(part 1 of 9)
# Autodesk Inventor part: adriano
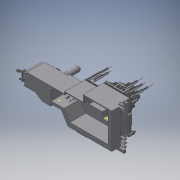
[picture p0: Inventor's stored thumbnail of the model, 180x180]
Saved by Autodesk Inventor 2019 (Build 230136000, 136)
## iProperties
Created: 2014-11
Part Number: adriano
Material: 一般
Document SubType Name: Modeling
Designer: Kikut
Density: 1 g/cm^3
Appearance: 既定
Author: Kikut
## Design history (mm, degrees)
sketch "スケッチ1"
  geometry: 1 further point
sketch "スケッチ2"
  geometry: L1 (-119.588, 39.314)-(-119.588, -40.686); L2 (-119.588, -40.686)-(-19.588, -40.686); L3 (-19.588, -40.686)-(-4.588, -15.686); L4 (-4.588, -15.686)-(20.412, -15.686); L5 (20.412, -15.686)-(20.412, 19.314); L6 (20.412, 19.314)-(-11.588, 19.314); L7 (-11.588, 19.314)-(-11.588, 24.314); L8 (-11.588, 24.314)-(-54.588, 24.314); L9 (-54.588, 24.314)-(-54.588, 39.314); L10 (-54.588, 39.314)-(-119.588, 39.314); 1 further point
  constraints: 20 end point, 7 parallel, 1 perpendicular, 1 vertical
  dimensions: "d0" = 80 distance of L1.start L1.end; "d2" = 100 distance of L1.end L2.end; "d3" = 25 distance of L3.end L4.end; "d4" = 35 distance of L4.end L5.end; "d5" = 65 distance of L9.end L1.start; "d6" = 15 distance of L8.end L9.end; "d7" = 43 distance of L7.end L8.end; "d8" = 32 distance of L5.end L6.end; "d9" = 5 distance of L6.end L7.end
extrude "押し出し1" new body sketch "スケッチ2" distance "d10" = 20; taper "d11" = 0 deg
sketch "スケッチ3"
  geometry: L1 (119.588, -39.314)-(119.588, 40.686) reference; L2 (119.588, 40.686)-(19.588, 40.686) reference; L3 (19.588, 40.686)-(4.588, 15.686) reference; L4 (-20.412, 15.686)-(-20.412, -19.314) reference; L5 (-20.412, -19.314)-(11.588, -19.314) reference; L6 (11.588, -19.314)-(11.588, -24.314) reference; L7 (11.588, -24.314)-(54.588, -24.314) reference; L8 (54.588, -24.314)-(54.588, -39.314) reference; L9 (54.588, -39.314)-(119.588, -39.314) reference; L10 (-20.412, -19.314)-(11.588, -19.314); L11 (11.588, -19.314)-(11.588, -24.314); L12 (11.588, -24.314)-(54.588, -24.314); L13 (54.588, -24.314)-(54.588, -39.314); L14 (54.588, -39.314)-(114.588, -39.314); L15 (114.588, -39.314)-(114.588, 32.686); L16 (114.588, 32.686)-(24.588, 32.686); L17 (24.588, 32.686)-(11.388, 10.686); L18 (11.388, 10.686)-(-20.412, 10.686); L19 (-20.412, 10.686)-(-20.412, -19.314); 1 further point
  constraints: 20 end point, 4 parallel, 4 perpendicular, 2 collinear
  dimensions: "d12" = 30 distance of L18.end L10.start; "d14" = 0 distance between parallel lines of L5 L10; "d15" = 0 distance between parallel lines of L11 L6; "d16" = 0 distance between parallel lines of L12 L7; "d17" = 0 distance between parallel lines of L13 L8; "d18" = 0 distance between parallel lines of L14 L9; "d19" = 5 distance between parallel lines of L1 L15; "d20" = 8 distance between parallel lines of L16 L2; "d21" = 0 distance between parallel lines of L4 L19; "d22" = 90 distance of L15.end L16.end; "d98" = 31.8 distance of L17.end L18.end (derived)
extrude "押し出し2" join sketch "スケッチ3" distance "d23" = 30; taper "d24" = 0 deg
sketch "スケッチ4"
  geometry: L1 (119.588, -39.314)-(119.588, 40.686) reference; L2 (119.588, 40.686)-(19.588, 40.686) reference; L3 (24.588, 32.686)-(114.588, 32.686) reference; L4 (38.588, 40.686)-(103.588, 40.686); L5 (103.588, 40.686)-(103.588, 32.686); L6 (103.588, 32.686)-(38.588, 32.686); L7 (38.588, 32.686)-(38.588, 40.686); 1 further point
  constraints: 8 end point, 2 parallel, 1 horizontal, 1 perpendicular, 1 point on line
  dimensions: "d25" = 0 distance between parallel lines of L3 L6; "d26" = 16 distance between parallel lines of L1 L5; "d27" = 65 distance between parallel lines of L5 L7
extrude "step00" join sketch "スケッチ4" distance "d28" = 1; taper "d29" = 0 deg
sketch "スケッチ5"
  geometry: L1 (38.588, 40.686)-(38.588, 32.686) reference; L2 (103.588, 32.686)-(38.588, 32.686) reference; L3 (103.588, 32.686)-(103.588, 40.686) reference; L4 (103.588, 40.686)-(38.588, 40.686) reference; L5 (39.588, 40.686)-(102.588, 40.686); L6 (102.588, 40.686)-(102.588, 32.686); L7 (102.588, 32.686)-(39.588, 32.686); L8 (39.588, 32.686)-(39.588, 40.686); 1 further point
  constraints: 8 end point, 2 parallel, 2 point on line, 1 horizontal, 1 perpendicular
  dimensions: "d30" = 1 distance between parallel lines of L3 L6; "d31" = 1 distance between parallel lines of L8 L1
extrude "押し出し4" join sketch "スケッチ5" distance "d32" = 1; taper "d33" = 0 deg
sketch "スケッチ6"
  geometry: L1 (102.588, 32.686)-(102.588, 40.686) reference; L2 (102.588, 40.686)-(39.588, 40.686) reference; L3 (39.588, 40.686)-(39.588, 32.686) reference; L4 (102.588, 32.686)-(39.588, 32.686) reference; L5 (40.588, 40.686)-(101.588, 40.686); L6 (101.588, 40.686)-(101.588, 32.686); L7 (101.588, 32.686)-(40.588, 32.686); L8 (40.588, 32.686)-(40.588, 40.686); 1 further point
  constraints: 8 end point, 2 parallel, 2 point on line, 1 horizontal, 1 perpendicular
  dimensions: "d34" = 1 distance between parallel lines of L8 L3; "d35" = 1 distance between parallel lines of L1 L6
extrude "押し出し5" join sketch "スケッチ6" distance "d36" = 1; taper "d37" = 0 deg
sketch "スケッチ7"
  geometry: L1 (40.588, 40.686)-(40.588, 32.686) reference; L2 (101.588, 32.686)-(40.588, 32.686) reference; L3 (101.588, 32.686)-(101.588, 40.686) reference; L4 (101.588, 40.686)-(40.588, 40.686) reference; L5 (41.588, 40.686)-(100.588, 40.686); L6 (100.588, 40.686)-(100.588, 32.686); L7 (100.588, 32.686)-(41.588, 32.686); L8 (41.588, 32.686)-(41.588, 40.686); 1 further point
  constraints: 8 end point, 2 parallel, 2 point on line, 1 horizontal, 1 perpendicular
  dimensions: "d38" = 1 distance between parallel lines of L8 L1; "d39" = 1 distance between parallel lines of L3 L6
extrude "押し出し6" join sketch "スケッチ7" distance "d40" = 1; taper "d41" = 0 deg
sketch "スケッチ8"
  geometry: L1 (100.588, 32.686)-(100.588, 40.686) reference; L2 (100.588, 40.686)-(41.588, 40.686) reference; L3 (41.588, 40.686)-(41.588, 32.686) reference; L4 (100.588, 32.686)-(41.588, 32.686) reference; L5 (42.588, 40.686)-(99.588, 40.686); L6 (99.588, 40.686)-(99.588, 32.686); L7 (99.588, 32.686)-(42.588, 32.686); L8 (42.588, 32.686)-(42.588, 40.686); 1 further point
  constraints: 8 end point, 2 parallel, 2 point on line, 1 horizontal, 1 perpendicular
  dimensions: "d42" = 1 distance between parallel lines of L8 L3; "d43" = 1 distance between parallel lines of L1 L6
extrude "押し出し7" join sketch "スケッチ8" distance "d44" = 1; taper "d45" = 0 deg
sketch "スケッチ9"
  geometry: L1 (42.588, 40.686)-(42.588, 32.686) reference; L2 (99.588, 32.686)-(42.588, 32.686) reference; L3 (99.588, 32.686)-(99.588, 40.686) reference; L4 (99.588, 40.686)-(42.588, 40.686) reference; L5 (43.588, 40.686)-(98.588, 40.686); L6 (98.588, 40.686)-(98.588, 32.686); L7 (98.588, 32.686)-(43.588, 32.686); L8 (43.588, 32.686)-(43.588, 40.686); 1 further point
  constraints: 8 end point, 2 parallel, 2 point on line, 1 horizontal, 1 perpendicular
  dimensions: "d46" = 1 distance between parallel lines of L8 L1; "d47" = 1 distance between parallel lines of L3 L6
extrude "押し出し8" join sketch "スケッチ9" distance "d48" = 1; taper "d49" = 0 deg
sketch "スケッチ10"
  geometry: L1 (98.588, 32.686)-(98.588, 40.686) reference; L2 (98.588, 40.686)-(43.588, 40.686) reference; L3 (43.588, 40.686)-(43.588, 32.686) reference; L4 (98.588, 32.686)-(43.588, 32.686) reference; L5 (44.588, 40.686)-(97.588, 40.686); L6 (97.588, 40.686)-(97.588, 32.686); L7 (97.588, 32.686)-(44.588, 32.686); L8 (44.588, 32.686)-(44.588, 40.686); 1 further point
  constraints: 8 end point, 2 parallel, 2 point on line, 1 horizontal, 1 perpendicular
  dimensions: "d50" = 1 distance between parallel lines of L3 L8; "d51" = 1 distance between parallel lines of L1 L6
extrude "押し出し9" join sketch "スケッチ10" distance "d52" = 1; taper "d53" = 0 deg
sketch "スケッチ11"
  geometry: L1 (44.588, 40.686)-(44.588, 32.686) reference; L2 (97.588, 32.686)-(44.588, 32.686) reference; L3 (97.588, 32.686)-(97.588, 40.686) reference; L4 (97.588, 40.686)-(44.588, 40.686) reference; L5 (45.588, 40.686)-(96.588, 40.686); L6 (96.588, 40.686)-(96.588, 32.686); L7 (96.588, 32.686)-(45.588, 32.686); L8 (45.588, 32.686)-(45.588, 40.686); 1 further point
  constraints: 8 end point, 2 parallel, 2 point on line, 1 horizontal, 1 perpendicular
  dimensions: "d54" = 1 distance between parallel lines of L1 L8; "d55" = 1 distance between parallel lines of L3 L6
extrude "押し出し10" join sketch "スケッチ11" distance "d56" = 1; taper "d57" = 0 deg
sketch "スケッチ12"
  geometry: L1 (96.588, 32.686)-(96.588, 40.686) reference; L2 (96.588, 40.686)-(45.588, 40.686) reference; L3 (45.588, 40.686)-(45.588, 32.686) reference; L4 (96.588, 32.686)-(45.588, 32.686) reference; L5 (46.588, 40.686)-(95.588, 40.686); L6 (95.588, 40.686)-(95.588, 32.686); L7 (95.588, 32.686)-(46.588, 32.686); L8 (46.588, 32.686)-(46.588, 40.686); 1 further point
  constraints: 8 end point, 2 parallel, 2 point on line, 1 horizontal, 1 perpendicular
  dimensions: "d58" = 1 distance between parallel lines of L8 L3; "d59" = 1 distance between parallel lines of L1 L6
extrude "押し出し11" join sketch "スケッチ12" distance "d60" = 1; taper "d61" = 0 deg
sketch "スケッチ13"
  geometry: L1 (46.588, 40.686)-(46.588, 32.686) reference; L2 (95.588, 32.686)-(46.588, 32.686) reference; L3 (95.588, 32.686)-(95.588, 40.686) reference; L4 (95.588, 40.686)-(46.588, 40.686) reference; L5 (47.588, 40.686)-(94.588, 40.686); L6 (94.588, 40.686)-(94.588, 32.686); L7 (94.588, 32.686)-(47.588, 32.686); L8 (47.588, 32.686)-(47.588, 40.686); 1 further point
  constraints: 8 end point, 2 parallel, 2 point on line, 1 horizontal, 1 perpendicular
  dimensions: "d62" = 1 distance between parallel lines of L8 L1; "d63" = 1 distance between parallel lines of L3 L6
extrude "押し出し12" join sketch "スケッチ13" distance "d64" = 1; taper "d65" = 0 deg
sketch "スケッチ14"
  geometry: L1 (94.588, 32.686)-(94.588, 40.686) reference; L2 (94.588, 40.686)-(47.588, 40.686) reference; L3 (47.588, 40.686)-(47.588, 32.686) reference; L4 (94.588, 32.686)-(47.588, 32.686) reference; L5 (48.588, 40.686)-(93.588, 40.686); L6 (93.588, 40.686)-(93.588, 32.686); L7 (93.588, 32.686)-(48.588, 32.686); L8 (48.588, 32.686)-(48.588, 40.686); 1 further point
  constraints: 8 end point, 2 parallel, 2 point on line, 1 horizontal, 1 perpendicular
  dimensions: "d66" = 1 distance between parallel lines of L8 L3; "d67" = 1 distance between parallel lines of L1 L6
extrude "押し出し13" join sketch "スケッチ14" distance "d68" = 1; taper "d69" = 0 deg
sketch "スケッチ15"
  geometry: L1 (48.588, 40.686)-(48.588, 32.686) reference; L2 (93.588, 32.686)-(48.588, 32.686) reference; L3 (93.588, 32.686)-(93.588, 40.686) reference; L4 (93.588, 40.686)-(48.588, 40.686) reference; L5 (49.588, 40.686)-(92.588, 40.686); L6 (92.588, 40.686)-(92.588, 32.686); L7 (92.588, 32.686)-(49.588, 32.686); L8 (49.588, 32.686)-(49.588, 40.686); 1 further point
  constraints: 8 end point, 2 parallel, 2 point on line, 1 horizontal, 1 perpendicular
  dimensions: "d70" = 1 distance between parallel lines of L8 L1; "d71" = 1 distance between parallel lines of L6 L3
extrude "押し出し14" join sketch "スケッチ15" distance "d72" = 1; taper "d73" = 0 deg
sketch "スケッチ16"
  geometry: L1 (92.588, 32.686)-(92.588, 40.686) reference; L2 (92.588, 40.686)-(49.588, 40.686) reference; L3 (49.588, 40.686)-(49.588, 32.686) reference; L4 (92.588, 32.686)-(49.588, 32.686) reference; L5 (50.588, 40.686)-(91.588, 40.686); L6 (91.588, 40.686)-(91.588, 32.686); L7 (91.588, 32.686)-(50.588, 32.686); L8 (50.588, 32.686)-(50.588, 40.686); 1 further point
  constraints: 8 end point, 2 parallel, 2 point on line, 1 horizontal, 1 perpendicular
  dimensions: "d74" = 1 distance between parallel lines of L8 L3; "d75" = 1 distance between parallel lines of L1 L6
extrude "押し出し15" join sketch "スケッチ16" distance "d76" = 1; taper "d77" = 0 deg
sketch "スケッチ17"
  geometry: L1 (50.588, 40.686)-(50.588, 32.686) reference; L2 (91.588, 32.686)-(50.588, 32.686) reference; L3 (91.588, 32.686)-(91.588, 40.686) reference; L4 (91.588, 40.686)-(50.588, 40.686) reference; L5 (51.588, 40.686)-(90.588, 40.686); L6 (90.588, 40.686)-(90.588, 32.686); L7 (90.588, 32.686)-(51.588, 32.686); L8 (51.588, 32.686)-(51.588, 40.686); 1 further point
  constraints: 8 end point, 2 parallel, 2 point on line, 1 horizontal, 1 perpendicular
  dimensions: "d78" = 1 distance between parallel lines of L8 L1; "d79" = 1 distance between parallel lines of L3 L6
extrude "押し出し16" join sketch "スケッチ17" distance "d80" = 1; taper "d81" = 0 deg
sketch "スケッチ18"
  geometry: L1 (90.588, 32.686)-(90.588, 40.686) reference; L2 (90.588, 40.686)-(51.588, 40.686) reference; L3 (51.588, 40.686)-(51.588, 32.686) reference; L4 (90.588, 32.686)-(51.588, 32.686) reference; L5 (52.588, 40.686)-(89.588, 40.686); L6 (89.588, 40.686)-(89.588, 32.686); L7 (89.588, 32.686)-(52.588, 32.686); L8 (52.588, 32.686)-(52.588, 40.686); 1 further point
  constraints: 8 end point, 2 parallel, 2 point on line, 1 horizontal, 1 perpendicular
  dimensions: "d82" = 1 distance between parallel lines of L8 L3; "d83" = 1 distance between parallel lines of L1 L6
extrude "押し出し17" join sketch "スケッチ18" distance "d84" = 1; taper "d85" = 0 deg
sketch "スケッチ19"
  geometry: L1 (52.588, 40.686)-(52.588, 32.686) reference; L2 (89.588, 32.686)-(52.588, 32.686) reference; L3 (89.588, 32.686)-(89.588, 40.686) reference; L4 (89.588, 40.686)-(52.588, 40.686) reference; L5 (53.588, 40.686)-(88.588, 40.686); L6 (88.588, 40.686)-(88.588, 32.686); L7 (88.588, 32.686)-(53.588, 32.686); L8 (53.588, 32.686)-(53.588, 40.686); 1 further point
  constraints: 8 end point, 2 parallel, 2 point on line, 1 horizontal, 1 perpendicular
  dimensions: "d86" = 1 distance between parallel lines of L8 L1; "d87" = 1 distance between parallel lines of L3 L6
extrude "押し出し18" join sketch "スケッチ19" distance "d88" = 1; taper "d89" = 0 deg
sketch "スケッチ20"
  geometry: L1 (88.588, 32.686)-(88.588, 40.686) reference; L2 (88.588, 40.686)-(53.588, 40.686) reference; L3 (53.588, 40.686)-(53.588, 32.686) reference; L4 (88.588, 32.686)-(53.588, 32.686) reference; L5 (54.588, 40.686)-(87.588, 40.686); L6 (87.588, 40.686)-(87.588, 32.686); L7 (87.588, 32.686)-(54.588, 32.686); L8 (54.588, 32.686)-(54.588, 40.686); 1 further point
  constraints: 8 end point, 2 parallel, 2 point on line, 1 horizontal, 1 perpendicular
  dimensions: "d90" = 1 distance between parallel lines of L3 L8; "d91" = 1 distance between parallel lines of L1 L6
extrude "step" join sketch "スケッチ20" distance "d92" = 1; taper "d93" = 0 deg
sketch "スケッチ21"
  geometry: L1 (72, 0)-(0, 0) reference; L2 (72, 0)-(72, 30) reference; L3 (0, 30)-(72, 30) reference; L4 (0, 0)-(0, 30) reference; L5 (22, 30)-(50, 30); L6 (50, 30)-(50, 0); L7 (50, 0)-(22, 0); L8 (22, 0)-(22, 30); 1 further point
  constraints: 8 end point, 2 parallel, 2 point on line, 1 horizontal, 1 perpendicular
  dimensions: "d94" = 22 distance between parallel lines of L8 L4; "d95" = 22 distance between parallel lines of L2 L6
extrude "押し出し20" cut sketch "スケッチ21" distance "d96" = 1; taper "d97" = 0 deg
sketch "スケッチ22"
  geometry: L1 (-20.412, 10.686)-(11.588, 10.686); L2 (11.588, 10.686)-(11.588, -19.314); L3 (11.588, -19.314)-(-20.412, -19.314); L4 (-20.412, -19.314)-(-20.412, 10.686); 1 further point
  constraints: 8 end point, 2 parallel, 1 horizontal, 1 perpendicular
extrude "押し出し21" cut sketch "スケッチ22" distance "d99" = 4; taper "d100" = 0 deg
sketch "スケッチ23"
  geometry: L1 (11.588, 10.686)-(11.588, -24.314) reference; L2 (11.588, -24.314)-(54.588, -24.314) reference; L3 (54.588, -24.314)-(54.588, -39.314) reference; L4 (54.588, -39.314)-(114.588, -39.314) reference; L5 (114.588, -39.314)-(114.588, -17.314) reference; L6 (113.588, -17.314)-(113.588, 10.686) reference; L7 (114.588, 10.686)-(114.588, 32.686) reference; L8 (114.588, 32.686)-(24.588, 32.686) reference; L9 (24.588, 32.686)-(11.388, 10.686) reference; L10 (113.588, 31.686)-(113.588, 11.686); L11 (113.588, 11.686)-(112.588, 11.686); L12 (112.588, 11.686)-(112.588, -18.314); L13 (112.588, -18.314)-(113.588, -18.314); L14 (113.588, -18.314)-(113.588, -38.314); L15 (113.588, -38.314)-(55.588, -38.314); L16 (55.588, -38.314)-(55.588, -23.314); L17 (55.588, -23.314)-(11.588, -23.314); L18 (11.588, 9.076)-(25.154, 31.686); L19 (25.154, 31.686)-(113.588, 31.686); 1 further point
  constraints: 20 end point, 7 parallel, 3 perpendicular, 2 point on line
  dimensions: "d101" = 1 distance between parallel lines of L8 L19; "d102" = 1 distance between parallel lines of L7 L10; "d103" = 1 distance between parallel lines of L6 L12; "d104" = 1 distance between parallel lines of L5 L14; "d105" = 1 distance between parallel lines of L4 L15; "d106" = 1 distance between parallel lines of L16 L3; "d107" = 1 distance between parallel lines of L2 L17; "d108" = 1 distance between parallel lines of L9 L18; "d109" = 1 horizontal distance of L6.end L11.end; "d110" = 1 horizontal distance of L5.end L13.end
extrude "押し出し22" cut sketch "スケッチ23" distance "d111" = 4; taper "d112" = 0 deg
sketch "スケッチ24"
  geometry: L1 (-22, 30)-(-22, 0) reference; L2 (0, 0)-(-22, 0) reference; L3 (0, 0)-(0, 30) reference; L4 (-17, 0)-(-5, 0); A1 r 6 centre (-11, 0) between (-5, 0) and (-17, 0); 1 further point
  constraints: 2 end point, 2 point on circle, 1 centre point, 1 collinear, 1 midpoint, 1 point on line
  dimensions: "d113" = 5 distance from line of L4.start L1; "d114" = 5 distance from line of L3 L4.end
extrude "押し出し23" cut sketch "スケッチ24" distance "d115" = 0.5; taper "d116" = 0 deg
sketch "スケッチ25"
  geometry: L1 (-5, 0)-(-17, 0) reference; L2 (-16, 0)-(-6, 0); A1 r 6 centre (-11, 0) between (-5, 0) and (-17, 0) reference; A2 r 5 centre (-11, 0) between (-6, 0) and (-16, 0); 1 further point
  constraints: 2 end point, 2 point on circle, 1 centre point, 1 coincident, 1 collinear, 1 point on line
  dimensions: "d117" = 1 radial gap between concentric circles of A1 A2
extrude "押し出し24" cut sketch "スケッチ25" distance "d118" = 1; taper "d119" = 0 deg
sketch "スケッチ26"
  geometry: L1 (-6, 0)-(-16, 0) reference; L2 (-11.8, 4.936)-(-11.8, 0); L3 (-10.2, 0)-(-10.2, 4.936); L4 (-15, 3)-(-15, 0); L5 (-13.4, 0)-(-13.4, 4.386); L6 (-7, 3)-(-7, 0); L7 (-8.6, 0)-(-8.6, 4.386); A1 r 5 centre (-11, 0) between (-6, 0) and (-16, 0) reference; A2 r 5 centre (-11, 0) between (-10.2, 4.936) and (-11.8, 4.936); A3 r 5 centre (-11, 0) between (-13.4, 4.386) and (-15, 3); A4 r 5 centre (-11, 0) between (-6.875, 2.825) and (-8.6, 4.386); 1 further point
  constraints: 12 end point, 10 point on circle, 6 point on line, 3 centre point, 3 coincident, 3 parallel, 3 perpendicular, 2 concentric
  dimensions: "d120" = 0.8 distance from line of A1.centre L2; "d121" = 0.8 distance from line of A1.centre L3; "d122" = 1.6 distance between parallel lines of L2 L5; "d123" = 1.6 distance between parallel lines of L5 L4; "d124" = 1.6 distance between parallel lines of L7 L3; "d125" = 1.6 distance between parallel lines of L7 L6
extrude "押し出し25" cut sketch "スケッチ26" distance "d126" = 4; taper "d127" = 0 deg
sketch "スケッチ27"
  geometry: L1 (119.588, 39.314)-(119.588, -40.686) reference; L2 (54.588, 39.314)-(119.588, 39.314) reference; L3 (54.588, 24.314)-(54.588, 39.314) reference; L4 (11.588, 24.314)-(54.588, 24.314) reference; L5 (11.588, 19.314)-(11.588, 24.314) reference; L6 (-20.412, 19.314)-(11.588, 19.314) reference; L7 (-20.412, -15.686)-(-20.412, 19.314) reference; L8 (4.588, -15.686)-(-20.412, -15.686) reference; L9 (19.588, -40.686)-(4.588, -15.686) reference; L10 (119.588, -40.686)-(19.588, -40.686) reference; L11 (56.588, 37.314)-(111.588, 37.314); L12 (111.588, 37.314)-(111.588, -30.686); L13 (111.588, -30.686)-(24.03, -30.686); L14 (24.03, -30.686)-(9.03, -5.686); L15 (9.03, -5.686)-(-18.412, -5.686); L16 (-18.412, -5.686)-(-18.412, 17.314); L17 (-18.412, 17.314)-(13.588, 17.314); L18 (13.588, 17.314)-(13.588, 22.314); L19 (13.588, 22.314)-(56.588, 22.314); L20 (56.588, 22.314)-(56.588, 37.314); 1 further point
  constraints: 20 end point, 9 parallel, 1 perpendicular
  dimensions: "d128" = 2 distance between parallel lines of L2 L11; "d129" = 2 distance between parallel lines of L20 L3; "d130" = 2 distance between parallel lines of L19 L4; "d131" = 2 distance between parallel lines of L18 L5; "d132" = 2 distance between parallel lines of L17 L6; "d133" = 2 distance between parallel lines of L16 L7; "d134" = 10 distance between parallel lines of L8 L15; "d135" = 8 distance between parallel lines of L1 L12; "d136" = 10 distance between parallel lines of L10 L13
extrude "押し出し26" cut sketch "スケッチ27" distance "d137" = 36; taper "d138" = 0 deg
sketch "スケッチ28"
  geometry: L1 (22, 0)-(22, 30) reference; L2 (0, 30)-(22, 30); L3 (22, 30)-(22, 26); L4 (22, 26)-(0, 26); L5 (0, 26)-(0, 30); 1 further point
  constraints: 8 end point, 2 parallel, 1 horizontal, 1 perpendicular, 1 point on line
  dimensions: "d139" = 4 distance of L4.end L2.start
extrude "押し出し27" cut sketch "スケッチ28" distance "d140" = 0.5; taper "d141" = 0 deg
sketch "スケッチ29"
  geometry: L1 (50, 30)-(50, 0) reference; L2 (22, 30)-(50, 30); L3 (50, 30)-(50, 26); L4 (50, 26)-(22, 26); L5 (22, 26)-(22, 30); 1 further point
  constraints: 8 end point, 2 parallel, 1 horizontal, 1 perpendicular, 1 point on line
  dimensions: "d142" = 4 distance of L4.end L2.start
extrude "押し出し28" cut sketch "スケッチ29" distance "d143" = 0.5; taper "d144" = 0 deg
sketch "スケッチ30"
  geometry: L1 (0, 0)-(0, 30) reference; L2 (-22, 30)-(0, 30); L3 (0, 30)-(0, 26); L4 (0, 26)-(-22, 26); L5 (-22, 26)-(-22, 30); 1 further point
  constraints: 8 end point, 2 parallel, 1 horizontal, 1 perpendicular, 1 point on line
  dimensions: "d145" = 4 distance of L2.end L3.end
extrude "押し出し29" cut sketch "スケッチ30" distance "d147" = 0.5; taper "d148" = 0 deg
sketch "スケッチ31"
  geometry: L1 (0, 0)-(0, 30) reference; L2 (-89.5, 30)-(0, 30); L3 (0, 30)-(0, 26); L4 (0, 26)-(-89.5, 26); L5 (-89.5, 26)-(-89.5, 30); 1 further point
  constraints: 8 end point, 2 parallel, 1 horizontal, 1 perpendicular, 1 point on line
  dimensions: "d149" = 4 distance of L4.end L2.start
extrude "押し出し30" cut sketch "スケッチ31" distance "d150" = 0.5; taper "d151" = 0 deg
sketch "スケッチ32"
  geometry: L1 (0, 26)-(0, 30) reference; L2 (-25.656, 30)-(0, 30) reference; L3 (-25.656, 30)-(0, 30); L4 (0, 30)-(0, 26); L5 (0, 26)-(-25.656, 26); L6 (-25.656, 26)-(-25.656, 30); 1 further point
  constraints: 8 end point, 2 parallel, 1 horizontal, 1 perpendicular
extrude "押し出し31" cut sketch "スケッチ32" distance "d152" = 0.5; taper "d153" = 0 deg
sketch "スケッチ33"
  geometry: L1 (59.5, 46)-(59.5, 50) reference; L2 (0, 50)-(59.5, 50) reference; L3 (0, 50)-(59.5, 50); L4 (59.5, 50)-(59.5, 46); L5 (59.5, 46)-(0, 46); L6 (0, 46)-(0, 50); 1 further point
  constraints: 8 end point, 2 parallel, 1 horizontal, 1 perpendicular
extrude "押し出し32" cut sketch "スケッチ33" distance "d154" = 0.5; taper "d155" = 0 deg; dims "d1298" = 0
sketch "スケッチ34"
  geometry: L1 (14.5, 46)-(14.5, 50) reference; L2 (0, 50)-(14.5, 50) reference; L3 (14.5, 46)-(0, 46); L4 (0, 46)-(0, 50); L5 (0, 50)-(14.5, 50); L6 (14.5, 50)-(14.5, 46); 1 further point
  constraints: 8 end point, 2 parallel, 1 horizontal, 1 perpendicular
extrude "押し出し33" cut sketch "スケッチ34" distance "d156" = 0.5; taper "d157" = 0 deg
sketch "スケッチ35"
  geometry: L1 (43, 0)-(43, 46) reference; L2 (0, 50)-(43, 50); L3 (43, 50)-(43, 46); L4 (43, 46)-(0, 46); L5 (0, 46)-(0, 50); L6 (43, 50)-(43.5, 50); L7 (43.5, 50)-(43.5, 46); L8 (43.5, 46)-(43, 46); L9 (43, 46)-(43, 50); 1 further point
  constraints: 16 end point, 4 parallel, 2 horizontal, 2 perpendicular, 1 point on line
  dimensions: "d591" = 4 distance of L4.end L2.start
extrude "押し出し34" cut sketch "スケッチ35" distance "d158" = 0.5; taper "d159" = 0 deg
sketch "スケッチ36"
  geometry: L1 (22, 26)-(0, 26) reference; L2 (0, 0)-(0, 26) reference; L3 (22, 0)-(22, 26) reference; L4 (5.5, 20)-(5.5, 14); L5 (5.5, 14)-(9.5, 14); L6 (9.5, 14)-(9.5, 20); L7 (12.5, 20)-(12.5, 14); L8 (12.5, 14)-(16.5, 14); L9 (16.5, 14)-(16.5, 20); A1 r 2 centre (7.5, 20) between (9.5, 20) and (5.5, 20); A2 r 2 centre (14.5, 20) between (16.5, 20) and (12.5, 20); 1 further point
  constraints: 12 end point, 4 parallel, 4 point on circle, 4 tangent, 2 centre point, 2 perpendicular
  dimensions: "d160" = 4 distance of L4.end L5.end; "d162" = 4 distance of L7.end L8.end; "d163" = 6 distance of L8.end L9.end; "d164" = 6 distance of L4.start L4.end; "d165" = 3 distance between parallel lines of L7 L6; "d166" = 5.5 distance between parallel lines of L2 L4; "d167" = 12 distance between parallel lines of L1 L5
extrude "押し出し35" cut sketch "スケッチ36" distance "d168" = 1; taper "d169" = 0 deg
sketch "スケッチ37"
  geometry: L1 (9.5, 14)-(5.5, 14) reference; L2 (6.02, 16.9)-(7.22, 16.9); L3 (7.22, 16.9)-(7.22, 14.7); L4 (7.22, 14.7)-(6.02, 14.7); L5 (6.02, 14.7)-(6.02, 16.9); L6 (7.82, 16.9)-(9.02, 16.9); L7 (9.02, 16.9)-(9.02, 14.7); L8 (9.02, 14.7)-(7.82, 14.7); L9 (7.82, 14.7)-(7.82, 16.9); L10 (6.02, 19.5)-(7.22, 19.5); L11 (7.22, 19.5)-(7.22, 17.5); L12 (7.22, 17.5)-(6.02, 17.5); L13 (6.02, 17.5)-(6.02, 19.5); L14 (7.82, 19.5)-(9.02, 19.5); L15 (9.02, 19.5)-(9.02, 17.5); L16 (9.02, 17.5)-(7.82, 17.5); L17 (7.82, 17.5)-(7.82, 19.5); L18 (7.25, 21.3)-(7.25, 20.1); L19 (7.25, 20.1)-(6.05, 20.1); L20 (7.75, 21.3)-(7.75, 20.1); L21 (7.75, 20.1)-(8.95, 20.1); A1 r 2 centre (7.5, 20) between (9.5, 20) and (5.5, 20) reference; A2 r 1.2 centre (7.25, 20.1) between (7.25, 21.3) and (6.05, 20.1); A3 r 1.2 centre (7.75, 20.1) between (8.95, 20.1) and (7.75, 21.3); 1 further point
  constraints: 40 end point, 9 parallel, 7 perpendicular, 4 horizontal, 4 point on circle, 2 centre point
  dimensions: "d170" = 1.2 distance of L3.end L4.end; "d172" = 1.2 distance of L7.end L8.end; "d173" = 0.6 distance between parallel lines of L9 L3; "d174" = 0.6 distance between parallel lines of L11 L17; "d175" = 1.2 distance of L15.end L16.end; "d176" = 0.5 distance between parallel lines of L20 L18; "d177" = 0.6 distance between parallel lines of L10 L19; "d179" = 0.25 distance from line of L18 A1.centre; "d180" = 1.2 distance of L18.end L19.end; "d181" = 1.2 distance of L20.end L21.end; "d182" = 1.2 distance of L11.end L12.end; "d183" = 2 distance of L14.end L15.end; "d184" = 0.6 distance between parallel lines of L14 L21; "d185" = 0.6 distance between parallel lines of L6 L16; "d186" = 0.6 distance between parallel lines of L2 L12; "d187" = 0.7 distance between parallel lines of L1 L4; "d189" = 2 distance of L12.end L10.start
extrude "押し出し36" cut sketch "スケッチ37" distance "d190" = 4; taper "d191" = 0 deg
sketch "スケッチ38"
  geometry: L1 (16.5, 14)-(12.5, 14) reference; L2 (13.098, 14.7)-(14.25, 14.7); L3 (14.25, 14.7)-(14.25, 16.9); L4 (14.25, 16.9)-(13.098, 16.9); L5 (13.098, 16.9)-(13.098, 14.7); L6 (14.25, 17.5)-(13.098, 17.5); L7 (13.098, 17.5)-(13.098, 19.5); L8 (13.098, 19.5)-(14.25, 19.5); L9 (14.25, 19.5)-(14.25, 17.5); L10 (14.75, 19.5)-(15.902, 19.5); L11 (15.902, 19.5)-(15.902, 17.5); L12 (15.902, 17.5)-(14.75, 17.5); L13 (14.75, 17.5)-(14.75, 19.5); L14 (15.902, 16.9)-(14.75, 16.9); L15 (14.75, 16.9)-(14.75, 14.7); L16 (14.75, 14.7)-(15.902, 14.7); L17 (15.902, 14.7)-(15.902, 16.9); L18 (13.098, 20.1)-(14.25, 20.1); L19 (14.25, 20.1)-(14.25, 21.252); L20 (14.75, 21.252)-(14.75, 20.1); L21 (14.75, 20.1)-(15.902, 20.1); A1 r 2 centre (14.5, 20) between (16.5, 20) and (12.5, 20) reference; A2 r 1.152 centre (14.25, 20.1) between (14.25, 21.252) and (13.098, 20.1); A3 r 1.152 centre (14.75, 20.1) between (15.902, 20.1) and (14.75, 21.252); 1 further point
  constraints: 40 end point, 9 parallel, 7 perpendicular, 4 horizontal, 4 point on circle, 2 centre point
  dimensions: "d192" = 0.7 distance between parallel lines of L2 L1; "d193" = 0.6 distance between parallel lines of L6 L4; "d194" = 0.6 distance between parallel lines of L18 L8; "d195" = 0.6 distance between parallel lines of L10 L21; "d196" = 0.6 distance between parallel lines of L14 L12; "d197" = 0.7 distance between parallel lines of L16 L1; "d198" = 0.5 distance between parallel lines of L13 L9; "d199" = 0.5 distance between parallel lines of L15 L3; "d200" = 0.25 distance from line of L19 A1.centre; "d201" = 0 distance between parallel lines of L19 L9; "d202" = 0 distance between parallel lines of L9 L3; "d203" = 0 distance between parallel lines of L17 L11; "d204" = 0 horizontal distance of L7.end L18.start; "d205" = 0 vertical distance of L19.end L20.start; "d206" = 0 distance from line of L21.end L11; "d207" = 2.2 distance of L16.end L14.start; "d208" = 2 distance of L6.end L7.end; "d209" = 2.2 distance of L4.end L2.start
extrude "押し出し37" cut sketch "スケッチ38" distance "d210" = 4; taper "d211" = 0 deg
sketch "スケッチ39"
  geometry: L1 (0.5, 30)-(0.5, 26) reference; L2 (22, 26)-(0.5, 26) reference; L3 (0.5, 30)-(22, 30) reference; L4 (1.3, 29.2)-(2.1, 29.2); L5 (2.1, 29.2)-(2.1, 26.8); L6 (2.1, 26.8)-(1.3, 26.8); L7 (1.3, 26.8)-(1.3, 29.2); L8 (2.9, 29.2)-(3.7, 29.2); L9 (3.7, 29.2)-(3.7, 26.8); L10 (3.7, 26.8)-(2.9, 26.8); L11 (2.9, 26.8)-(2.9, 29.2); L12 (4.5, 29.2)-(5.3, 29.2); L13 (5.3, 29.2)-(5.3, 26.8); L14 (5.3, 26.8)-(4.5, 26.8); L15 (4.5, 26.8)-(4.5, 29.2); L16 (6.1, 29.2)-(6.9, 29.2); L17 (6.9, 29.2)-(6.9, 26.8); L18 (6.9, 26.8)-(6.1, 26.8); L19 (6.1, 26.8)-(6.1, 29.2); L20 (7.7, 29.2)-(8.5, 29.2); L21 (8.5, 29.2)-(8.5, 26.8); L22 (8.5, 26.8)-(7.7, 26.8); L23 (7.7, 26.8)-(7.7, 29.2); L24 (9.3, 29.2)-(10.1, 29.2); L25 (10.1, 29.2)-(10.1, 26.8); L26 (10.1, 26.8)-(9.3, 26.8); L27 (9.3, 26.8)-(9.3, 29.2); L28 (10.9, 29.2)-(11.7, 29.2); L29 (11.7, 29.2)-(11.7, 26.8); L30 (11.7, 26.8)-(10.9, 26.8); L31 (10.9, 26.8)-(10.9, 29.2); L32 (12.5, 29.2)-(13.3, 29.2); L33 (13.3, 29.2)-(13.3, 26.8); L34 (13.3, 26.8)-(12.5, 26.8); L35 (12.5, 26.8)-(12.5, 29.2); L36 (14.1, 29.2)-(14.9, 29.2); L37 (14.9, 29.2)-(14.9, 26.8); L38 (14.9, 26.8)-(14.1, 26.8); L39 (14.1, 26.8)-(14.1, 29.2); L40 (15.7, 29.2)-(16.5, 29.2); L41 (16.5, 29.2)-(16.5, 26.8); L42 (16.5, 26.8)-(15.7, 26.8); L43 (15.7, 26.8)-(15.7, 29.2); L44 (17.3, 29.2)-(18.1, 29.2); L45 (18.1, 29.2)-(18.1, 26.8); L46 (18.1, 26.8)-(17.3, 26.8); L47 (17.3, 26.8)-(17.3, 29.2); L48 (18.9, 29.2)-(19.7, 29.2); L49 (19.7, 29.2)-(19.7, 26.8); L50 (19.7, 26.8)-(18.9, 26.8); L51 (18.9, 26.8)-(18.9, 29.2); L52 (20.5, 29.2)-(21.3, 29.2); L53 (21.3, 29.2)-(21.3, 26.8); L54 (21.3, 26.8)-(20.5, 26.8); L55 (20.5, 26.8)-(20.5, 29.2); 1 further point
  constraints: 104 end point, 26 parallel, 13 horizontal, 13 perpendicular
  dimensions: "d212" = 0.8 distance between parallel lines of L3 L4; "d213" = 0.8 distance between parallel lines of L2 L6; "d214" = 0.8 distance of L4.start L4.end; "d215" = 0.8 distance between parallel lines of L1 L7; "d216" = 0.8 distance of L8.start L8.end; "d217" = 0.8 distance between parallel lines of L11 L5; "d218" = 0.8 distance between parallel lines of L15 L9; "d219" = 0.8 distance of L12.start L12.end; "d220" = 0.8 distance between parallel lines of L19 L13; "d221" = 0.8 distance of L16.start L16.end; "d222" = 0.8 distance between parallel lines of L23 L17; "d223" = 0.8 distance of L20.start L20.end; "d224" = 0.8 distance between parallel lines of L27 L21; "d225" = 0.8 distance of L24.start L24.end; "d226" = 0.8 distance between parallel lines of L31 L25; "d227" = 0.8 distance of L28.start L28.end; "d228" = 0.8 distance between parallel lines of L35 L29; "d229" = 0.8 distance of L32.start L32.end; "d230" = 0.8 distance between parallel lines of L39 L33; "d231" = 0.8 distance of L36.start L36.end; "d232" = 0.8 distance between parallel lines of L43 L37; "d233" = 0.8 distance of L40.start L40.end; "d234" = 0 distance between parallel lines of L10 L6; "d235" = 0 distance between parallel lines of L14 L10; "d236" = 0 distance between parallel lines of L14 L18; "d237" = 0 distance between parallel lines of L22 L18; "d238" = 0 distance between parallel lines of L26 L22; "d239" = 0 distance between parallel lines of L30 L26; "d240" = 0 distance between parallel lines of L34 L30; "d241" = 0 distance between parallel lines of L38 L34; "d242" = 0 distance between parallel lines of L42 L38; "d243" = 0 distance between parallel lines of L8 L4; "d246" = 0.8 distance between parallel lines of L47 L41; "d247" = 0.8 distance of L44.start L44.end; "d248" = 0.8 distance between parallel lines of L51 L45; "d249" = 0.8 distance of L48.start L48.end; "d250" = 0.8 distance between parallel lines of L55 L49; "d251" = 0.8 distance of L52.start L52.end
extrude "押し出し38" cut sketch "スケッチ39" distance "d244" = 2; taper "d245" = 0 deg
sketch "スケッチ40"
  geometry: L1 (16.5, 29.2)-(16.5, 26.8) reference; L2 (17.3, 29.2)-(18.1, 29.2); L3 (18.1, 29.2)-(18.1, 26.8); L4 (18.1, 26.8)-(17.3, 26.8); L5 (17.3, 26.8)-(17.3, 29.2); L6 (18.9, 29.2)-(19.7, 29.2); L7 (19.7, 29.2)-(19.7, 26.8); L8 (19.7, 26.8)-(18.9, 26.8); L9 (18.9, 26.8)-(18.9, 29.2); L10 (20.5, 29.2)-(21.3, 29.2); L11 (21.3, 29.2)-(21.3, 26.8); L12 (21.3, 26.8)-(20.5, 26.8); L13 (20.5, 26.8)-(20.5, 29.2); 1 further point
  constraints: 24 end point, 6 parallel, 3 horizontal, 3 perpendicular
  dimensions: "d252" = 0.8 distance between parallel lines of L5 L1; "d253" = 0.8 distance of L2.start L2.end; "d254" = 0.8 distance between parallel lines of L9 L3; "d255" = 0.8 distance of L6.start L6.end; "d256" = 0.8 distance between parallel lines of L13 L7; "d257" = 0.8 distance of L10.start L10.end
extrude "押し出し39" cut sketch "スケッチ40" distance "d258" = 2; taper "d259" = 0 deg
sketch "スケッチ41"
  geometry: L1 (22, 26)-(22, 30) reference; L2 (22.8, 29.2)-(23.6, 29.2); L3 (23.6, 29.2)-(23.6, 26.8); L4 (23.6, 26.8)-(22.8, 26.8); L5 (22.8, 26.8)-(22.8, 29.2); L6 (24.4, 29.2)-(25.2, 29.2); L7 (25.2, 29.2)-(25.2, 26.8); L8 (25.2, 26.8)-(24.4, 26.8); L9 (24.4, 26.8)-(24.4, 29.2); L10 (26, 29.2)-(26.8, 29.2); L11 (26.8, 29.2)-(26.8, 26.8); L12 (26.8, 26.8)-(26, 26.8); L13 (26, 26.8)-(26, 29.2); L14 (27.6, 29.2)-(28.4, 29.2); L15 (28.4, 29.2)-(28.4, 26.8); L16 (28.4, 26.8)-(27.6, 26.8); L17 (27.6, 26.8)-(27.6, 29.2); L18 (29.2, 29.2)-(30, 29.2); L19 (30, 29.2)-(30, 26.8); L20 (30, 26.8)-(29.2, 26.8); L21 (29.2, 26.8)-(29.2, 29.2); L22 (30.8, 29.2)-(31.6, 29.2); L23 (31.6, 29.2)-(31.6, 26.8); L24 (31.6, 26.8)-(30.8, 26.8); L25 (30.8, 26.8)-(30.8, 29.2); L26 (32.4, 29.2)-(33.2, 29.2); L27 (33.2, 29.2)-(33.2, 26.8); L28 (33.2, 26.8)-(32.4, 26.8); L29 (32.4, 26.8)-(32.4, 29.2); L30 (34, 29.2)-(34.8, 29.2); L31 (34.8, 29.2)-(34.8, 26.8); L32 (34.8, 26.8)-(34, 26.8); L33 (34, 26.8)-(34, 29.2); L34 (35.6, 29.2)-(36.4, 29.2); L35 (36.4, 29.2)-(36.4, 26.8); L36 (36.4, 26.8)-(35.6, 26.8); L37 (35.6, 26.8)-(35.6, 29.2); L38 (37.2, 29.2)-(38, 29.2); L39 (38, 29.2)-(38, 26.8); L40 (38, 26.8)-(37.2, 26.8); L41 (37.2, 26.8)-(37.2, 29.2); L42 (38.8, 29.2)-(39.6, 29.2); L43 (39.6, 29.2)-(39.6, 26.8); L44 (39.6, 26.8)-(38.8, 26.8); L45 (38.8, 26.8)-(38.8, 29.2); L46 (40.4, 29.2)-(41.2, 29.2); L47 (41.2, 29.2)-(41.2, 26.8); L48 (41.2, 26.8)-(40.4, 26.8); L49 (40.4, 26.8)-(40.4, 29.2); L50 (42, 29.2)-(42.8, 29.2); L51 (42.8, 29.2)-(42.8, 26.8); L52 (42.8, 26.8)-(42, 26.8); L53 (42, 26.8)-(42, 29.2); L54 (43.6, 29.2)-(44.4, 29.2); L55 (44.4, 29.2)-(44.4, 26.8); L56 (44.4, 26.8)-(43.6, 26.8); L57 (43.6, 26.8)-(43.6, 29.2); L58 (45.2, 29.2)-(46, 29.2); L59 (46, 29.2)-(46, 26.8); L60 (46, 26.8)-(45.2, 26.8); L61 (45.2, 26.8)-(45.2, 29.2); L62 (46.8, 29.2)-(47.6, 29.2); L63 (47.6, 29.2)-(47.6, 26.8); L64 (47.6, 26.8)-(46.8, 26.8)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; 1 further point
  constraints: 136 end point, 34 parallel, 17 horizontal, 17 perpendicular
  dimensions: "d260" = 0.8 distance between parallel lines of L1 L5; "d261" = 0.8 distance of L2.start L2.end; "d262" = 0.8 distance between parallel lines of L9 L3; "d263" = 0.8 distance of L6.start L6.end; "d264" = 0.8 distance between parallel lines of L13 L7; "d265" = 0.8 distance of L10.start L10.end; "d266" = 0.8 distance between parallel lines of L17 L11; "d267" = 0.8 distance of L14.start L14.end; "d268" = 0.8 distance between parallel lines of L21 L15; "d269" = 0.8 distance of L18.start L18.end; "d270" = 0.8 distance between parallel lines of L25 L19; "d271" = 0.8 distance of L22.start L22.end; "d272" = 0.8 distance between parallel lines of L29 L23; "d273" = 0.8 distance of L26.start L26.end; "d274" = 0.8 distance between parallel lines of L33 L27; "d275" = 0.8 distance of L30.start L30.end; "d276" = 0.8 distance between parallel lines of L37 L31; "d277" = 0.8 distance of L34.start L34.end; "d278" = 0.8 distance between parallel lines of L41 L35; "d279" = 0.8 distance of L38.start L38.end; "d280" = 0.8 distance between parallel lines of L45 L39; "d281" = 0.8 distance of L42.start L42.end; "d282" = 0.8 distance between parallel lines of L49 L43; "d283" = 0.8 distance of L46.start L46.end; "d284" = 0.8 distance between parallel lines of L53 L47; "d285" = 0.8 distance of L50.start L50.end; "d286" = 0.8 distance between parallel lines of L57 L51; "d287" = 0.8 distance of L54.start L54.end; "d288" = 0.8 distance between parallel lines of L61 L55; "d289" = 0.8 distance of L58.start L58.end; "d290" = 0.8 distance between parallel lines of L65 L59; "d291" = 0.8 distance of L62.start L62.end; "d292" = 0.8 distance between parallel lines of L69 L63; "d293" = 0.8 distance of L66.start L66.end; "d350" = 0.8 distance between parallel lines of L70 L2; "d351" = 0 distance between parallel lines of L6 L2; "d352" = 0.8 distance between parallel lines of L71 L4; "d353" = 0 distance between parallel lines of L8 L4; "d354" = 0 distance between parallel lines of L12 L8; "d355" = 0 distance between parallel lines of L12 L20; "d356" = 0 distance between parallel lines of L20 L16; "d357" = 0 distance between parallel lines of L24 L20; "d358" = 0 distance between parallel lines of L28 L24; "d359" = 0 distance between parallel lines of L32 L28; "d360" = 0 distance between parallel lines of L36 L32; "d361" = 0 distance between parallel lines of L40 L36; "d362" = 0 distance between parallel lines of L44 L40; "d363" = 0 distance between parallel lines of L48 L44; "d364" = 0 distance between parallel lines of L52 L48; "d365" = 0 distance between parallel lines of L56 L52; "d366" = 0 distance between parallel lines of L60 L56; "d367" = 0 distance between parallel lines of L64 L60; "d368" = 0 distance between parallel lines of L68 L64
extrude "押し出し40" cut sketch "スケッチ41" distance "d294" = 2; taper "d295" = 0 deg
sketch "スケッチ42"
  geometry: L1 (-22, 30)-(-0.5, 30) reference; L2 (-22, 26)-(-22, 30) reference; L3 (-0.5, 26)-(-22, 26) reference; L4 (-21.2, 29.2)-(-20.4, 29.2); L5 (-20.4, 29.2)-(-20.4, 26.8); L6 (-20.4, 26.8)-(-21.2, 26.8); L7 (-21.2, 26.8)-(-21.2, 29.2); L8 (-19.6, 29.2)-(-18.8, 29.2); L9 (-18.8, 29.2)-(-18.8, 26.8); L10 (-18.8, 26.8)-(-19.6, 26.8); L11 (-19.6, 26.8)-(-19.6, 29.2); L12 (-18, 29.2)-(-17.2, 29.2); L13 (-17.2, 29.2)-(-17.2, 26.8); L14 (-17.2, 26.8)-(-18, 26.8); L15 (-18, 26.8)-(-18, 29.2); L16 (-16.4, 29.2)-(-15.6, 29.2); L17 (-15.6, 29.2)-(-15.6, 26.8); L18 (-15.6, 26.8)-(-16.4, 26.8); L19 (-16.4, 26.8)-(-16.4, 29.2); L20 (-14.8, 29.2)-(-14, 29.2); L21 (-14, 29.2)-(-14, 26.8); L22 (-14, 26.8)-(-14.8, 26.8); L23 (-14.8, 26.8)-(-14.8, 29.2); L24 (-13.2, 29.2)-(-12.4, 29.2); L25 (-12.4, 29.2)-(-12.4, 26.8); L26 (-12.4, 26.8)-(-13.2, 26.8); L27 (-13.2, 26.8)-(-13.2, 29.2); L28 (-11.6, 29.2)-(-10.8, 29.2); L29 (-10.8, 29.2)-(-10.8, 26.8); L30 (-10.8, 26.8)-(-11.6, 26.8); L31 (-11.6, 26.8)-(-11.6, 29.2); L32 (-10, 29.2)-(-9.2, 29.2); L33 (-9.2, 29.2)-(-9.2, 26.8); L34 (-9.2, 26.8)-(-10, 26.8); L35 (-10, 26.8)-(-10, 29.2); L36 (-8.4, 29.2)-(-7.6, 29.2); L37 (-7.6, 29.2)-(-7.6, 26.8); L38 (-7.6, 26.8)-(-8.4, 26.8); L39 (-8.4, 26.8)-(-8.4, 29.2); L40 (-6.8, 29.2)-(-6, 29.2); L41 (-6, 29.2)-(-6, 26.8); L42 (-6, 26.8)-(-6.8, 26.8); L43 (-6.8, 26.8)-(-6.8, 29.2); L44 (-5.2, 29.2)-(-4.4, 29.2); L45 (-4.4, 29.2)-(-4.4, 26.8); L46 (-4.4, 26.8)-(-5.2, 26.8); L47 (-5.2, 26.8)-(-5.2, 29.2); L48 (-3.6, 29.2)-(-2.8, 29.2); L49 (-2.8, 29.2)-(-2.8, 26.8); L50 (-2.8, 26.8)-(-3.6, 26.8); L51 (-3.6, 26.8)-(-3.6, 29.2); L52 (-2, 29.2)-(-1.2, 29.2); L53 (-1.2, 29.2)-(-1.2, 26.8); L54 (-1.2, 26.8)-(-2, 26.8); L55 (-2, 26.8)-(-2, 29.2); 1 further point
  constraints: 104 end point, 26 parallel, 13 horizontal, 13 perpendicular
  dimensions: "d296" = 0.8 distance between parallel lines of L2 L7; "d297" = 0.8 distance between parallel lines of L11 L5; "d298" = 0.8 distance of L4.start L4.end; "d299" = 0.8 distance of L8.start L8.end; "d300" = 0.8 distance between parallel lines of L15 L9; "d301" = 0.8 distance of L12.start L12.end; "d302" = 0.8 distance between parallel lines of L19 L13; "d303" = 0.8 distance of L16.start L16.end; "d304" = 0.8 distance between parallel lines of L23 L17; "d305" = 0.8 distance of L20.start L20.end; "d306" = 0.8 distance between parallel lines of L27 L21; "d307" = 0.8 distance of L24.start L24.end; "d308" = 0.8 distance between parallel lines of L31 L25; "d309" = 0.8 distance of L28.start L28.end; "d310" = 0.8 distance between parallel lines of L35 L29; "d311" = 0.8 distance of L32.start L32.end; "d312" = 0.8 distance between parallel lines of L39 L33; "d313" = 0.8 distance of L36.start L36.end; "d314" = 0.8 distance between parallel lines of L43 L37; "d315" = 0.8 distance of L40.start L40.end; "d316" = 0.8 distance between parallel lines of L47 L41; "d317" = 0.8 distance of L44.start L44.end; "d318" = 0.8 distance between parallel lines of L51 L45; "d319" = 0.8 distance between parallel lines of L55 L49; "d320" = 0.8 distance of L48.start L48.end; "d321" = 0.8 distance of L52.start L52.end; "d322" = 0.8 distance between parallel lines of L52 L1; "d323" = 0 distance between parallel lines of L52 L48; "d324" = 0 distance between parallel lines of L48 L44; "d325" = 0 distance between parallel lines of L44 L40; "d326" = 0 distance between parallel lines of L40 L36; "d327" = 0 distance between parallel lines of L36 L32; "d328" = 0 distance between parallel lines of L32 L28; "d329" = 0 distance between parallel lines of L28 L24; "d330" = 0 distance between parallel lines of L24 L20; "d331" = 0 distance between parallel lines of L20 L16; "d332" = 0 distance between parallel lines of L16 L12; "d333" = 0 distance between parallel lines of L12 L8; "d334" = 0 distance between parallel lines of L8 L4; "d335" = 0 distance between parallel lines of L10 L6; "d336" = 0 distance between parallel lines of L14 L10; "d337" = 0 distance between parallel lines of L18 L14; "d338" = 0 distance between parallel lines of L22 L18; "d339" = 0 distance between parallel lines of L26 L22; "d340" = 0 distance between parallel lines of L30 L26; "d341" = 0 distance between parallel lines of L34 L30; "d342" = 0 distance between parallel lines of L38 L34; "d343" = 0 distance between parallel lines of L42 L38; "d344" = 0 distance between parallel lines of L46 L42; "d345" = 0 distance between parallel lines of L46 L50; "d346" = 0 distance between parallel lines of L54 L50; "d347" = 0.8 distance between parallel lines of L3 L54
extrude "押し出し41" cut sketch "スケッチ42" distance "d348" = 2; taper "d349" = 0 deg
sketch "スケッチ43"
  geometry: L1 (0.5, 50)-(0.5, 46) reference; L2 (59.5, 46)-(0.5, 46) reference; L3 (0.5, 50)-(59.5, 50) reference; L4 (1.5, 49.2)-(2.3, 49.2); L5 (2.3, 49.2)-(2.3, 46.8); L6 (2.3, 46.8)-(1.5, 46.8); L7 (1.5, 46.8)-(1.5, 49.2); L8 (3.1, 49.2)-(3.9, 49.2); L9 (3.9, 49.2)-(3.9, 46.8); L10 (3.9, 46.8)-(3.1, 46.8); L11 (3.1, 46.8)-(3.1, 49.2); L12 (4.7, 49.2)-(5.5, 49.2); L13 (5.5, 49.2)-(5.5, 46.8); L14 (5.5, 46.8)-(4.7, 46.8); L15 (4.7, 46.8)-(4.7, 49.2); L16 (6.3, 49.2)-(7.1, 49.2); L17 (7.1, 49.2)-(7.1, 46.8); L18 (7.1, 46.8)-(6.3, 46.8); L19 (6.3, 46.8)-(6.3, 49.2); L20 (7.9, 49.2)-(8.7, 49.2); L21 (8.7, 49.2)-(8.7, 46.8); L22 (8.7, 46.8)-(7.9, 46.8); L23 (7.9, 46.8)-(7.9, 49.2); L24 (9.5, 49.2)-(10.3, 49.2); L25 (10.3, 49.2)-(10.3, 46.8); L26 (10.3, 46.8)-(9.5, 46.8); L27 (9.5, 46.8)-(9.5, 49.2); L28 (11.1, 49.2)-(11.9, 49.2); L29 (11.9, 49.2)-(11.9, 46.8); L30 (11.9, 46.8)-(11.1, 46.8); L31 (11.1, 46.8)-(11.1, 49.2); L32 (12.7, 49.2)-(13.5, 49.2); L33 (13.5, 49.2)-(13.5, 46.8); L34 (13.5, 46.8)-(12.7, 46.8); L35 (12.7, 46.8)-(12.7, 49.2); L36 (15.9, 49.2)-(16.7, 49.2); L37 (16.7, 49.2)-(16.7, 46.8); L38 (16.7, 46.8)-(15.9, 46.8); L39 (15.9, 46.8)-(15.9, 49.2); L40 (17.5, 49.2)-(18.3, 49.2); L41 (18.3, 49.2)-(18.3, 46.8); L42 (18.3, 46.8)-(17.5, 46.8); L43 (17.5, 46.8)-(17.5, 49.2); L44 (19.1, 49.2)-(19.9, 49.2); L45 (19.9, 49.2)-(19.9, 46.8); L46 (19.9, 46.8)-(19.1, 46.8); L47 (19.1, 46.8)-(19.1, 49.2); L48 (20.7, 49.2)-(21.5, 49.2); L49 (21.5, 49.2)-(21.5, 46.8); L50 (21.5, 46.8)-(20.7, 46.8); L51 (20.7, 46.8)-(20.7, 49.2); L52 (23.9, 49.2)-(24.7, 49.2); L53 (24.7, 49.2)-(24.7, 46.8); L54 (24.7, 46.8)-(23.9, 46.8); L55 (23.9, 46.8)-(23.9, 49.2); L56 (25.5, 49.2)-(26.3, 49.2); L57 (26.3, 49.2)-(26.3, 46.8); L58 (26.3, 46.8)-(25.5, 46.8); L59 (25.5, 46.8)-(25.5, 49.2); L60 (27.1, 49.2)-(27.9, 49.2); L61 (27.9, 49.2)-(27.9, 46.8); L62 (27.9, 46.8)-(27.1, 46.8); L63 (27.1, 46.8)-(27.1, 49.2); L64 (28.7, 49.2)-(29.5, 49.2)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; 1 further point
  constraints: 288 end point, 72 parallel, 36 horizontal, 36 perpendicular
  dimensions: "d369" = 1 distance between parallel lines of L1 L7; "d370" = 0.8 distance of L4.start L4.end; "d371" = 0.8 distance between parallel lines of L11 L5; "d372" = 0.8 distance of L8.start L8.end; "d373" = 0.8 distance between parallel lines of L15 L9; "d374" = 0.8 distance of L12.start L12.end; "d375" = 0.8 distance between parallel lines of L19 L13; "d376" = 0.8 distance of L16.start L16.end; "d377" = 0.8 distance between parallel lines of L23 L17; "d378" = 0.8 distance of L20.start L20.end; "d379" = 0.8 distance between parallel lines of L27 L21; "d380" = 0.8 distance of L24.start L24.end; "d381" = 0.8 distance between parallel lines of L31 L25; "d382" = 0.8 distance of L28.start L28.end; "d383" = 0.8 distance between parallel lines of L35 L29; "d384" = 0.8 distance of L32.start L32.end; "d385" = 0.8 distance between parallel lines of L103 L33; "d386" = 0.8 distance of L100.start L100.end; "d387" = 0.8 distance between parallel lines of L39 L101; "d388" = 0.8 distance of L36.start L36.end; "d389" = 0.8 distance between parallel lines of L43 L37; "d390" = 0.8 distance of L40.start L40.end; "d391" = 0.8 distance between parallel lines of L47 L41; "d392" = 0.8 distance of L44.start L44.end; "d393" = 0.8 distance between parallel lines of L51 L45; "d394" = 0.8 distance of L48.start L48.end; "d395" = 0.8 distance between parallel lines of L107 L49; "d396" = 0.8 distance of L104.start L104.end; "d397" = 0.8 distance between parallel lines of L55 L105; "d398" = 0.8 distance of L52.start L52.end; "d399" = 0.8 distance between parallel lines of L59 L53; "d400" = 0.8 distance of L56.start L56.end; "d401" = 0.8 distance between parallel lines of L63 L57; "d402" = 0.8 distance of L60.start L60.end; "d403" = 0.8 distance between parallel lines of L67 L61; "d404" = 0.8 distance of L64.start L64.end; "d405" = 0.8 distance between parallel lines of L71 L65; "d406" = 0.8 distance of L68.start L68.end; "d407" = 0.8 distance between parallel lines of L75 L69; "d408" = 0.8 distance of L72.start L72.end; "d409" = 0.8 distance between parallel lines of L79 L73; "d410" = 0.8 distance of L76.start L76.end; "d411" = 0.8 distance between parallel lines of L83 L77; "d412" = 0.8 distance of L80.start L80.end; "d413" = 0.8 distance between parallel lines of L111 L81; "d414" = 0.8 distance of L108.start L108.end; "d415" = 0.8 distance between parallel lines of L87 L109; "d416" = 0.8 distance of L84.start L84.end; "d417" = 0.8 distance between parallel lines of L91 L85; "d418" = 0.8 distance of L88.start L88.end; "d419" = 0.8 distance between parallel lines of L95 L89; "d420" = 0.8 distance of L92.start L92.end; "d421" = 0.8 distance between parallel lines of L99 L93; "d422" = 0.8 distance of L96.start L96.end; "d423" = 0.8 distance between parallel lines of L115 L97; "d424" = 0.8 distance of L112.start L112.end; "d425" = 0.8 distance between parallel lines of L119 L113; "d426" = 0.8 distance of L116.start L116.end; "d427" = 0.8 distance between parallel lines of L123 L117; "d428" = 0.8 distance of L120.start L120.end; "d429" = 0.8 distance between parallel lines of L127 L121; "d430" = 0.8 distance of L124.start L124.end; "d431" = 0.8 distance between parallel lines of L131 L125; "d432" = 0.8 distance between parallel lines of L135 L129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
extrude "押し出し42" cut sketch "スケッチ43" distance "d478" = 2; taper "d479" = 0 deg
